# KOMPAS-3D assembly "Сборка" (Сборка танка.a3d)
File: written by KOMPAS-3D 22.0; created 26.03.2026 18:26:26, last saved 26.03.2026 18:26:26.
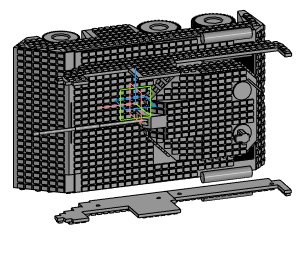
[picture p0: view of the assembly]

Document properties: Автор: Пользователь Windows; Полное имя файла: F:\Танк\Сборка танка.a3d

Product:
- Component [detail]: Деталь  | qty 1  | source file: Деталь.m3d
- Component [detail]: Деталь  | qty 1  | source file: Деталь_1.m3d
- Component [detail]: Деталь  | qty 4  | source file: Деталь_2.m3d
- Component [detail]: Деталь  | qty 1  | source file: Деталь_3.m3d
- Component [detail]: Деталь  | qty 2  | source file: Деталь_4.m3d
- Component [detail]: Деталь  | qty 5  | source file: Деталь_5.m3d
- Component [detail]: Деталь  | qty 2  | source file: Деталь_6.m3d
- Part/product: Сборка

Referenced files in F:\Танк\: Деталь.m3d, Деталь_1.m3d, Деталь_2.m3d, Деталь_3.m3d, Деталь_4.m3d, Деталь_5.m3d, Деталь_6.m3d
